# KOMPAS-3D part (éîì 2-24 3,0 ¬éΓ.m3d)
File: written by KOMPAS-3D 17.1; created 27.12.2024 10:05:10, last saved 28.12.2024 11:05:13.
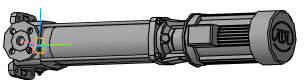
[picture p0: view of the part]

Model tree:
1. Операция без истории:4  (labels: ВМН 2-24 3,0 кВт)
